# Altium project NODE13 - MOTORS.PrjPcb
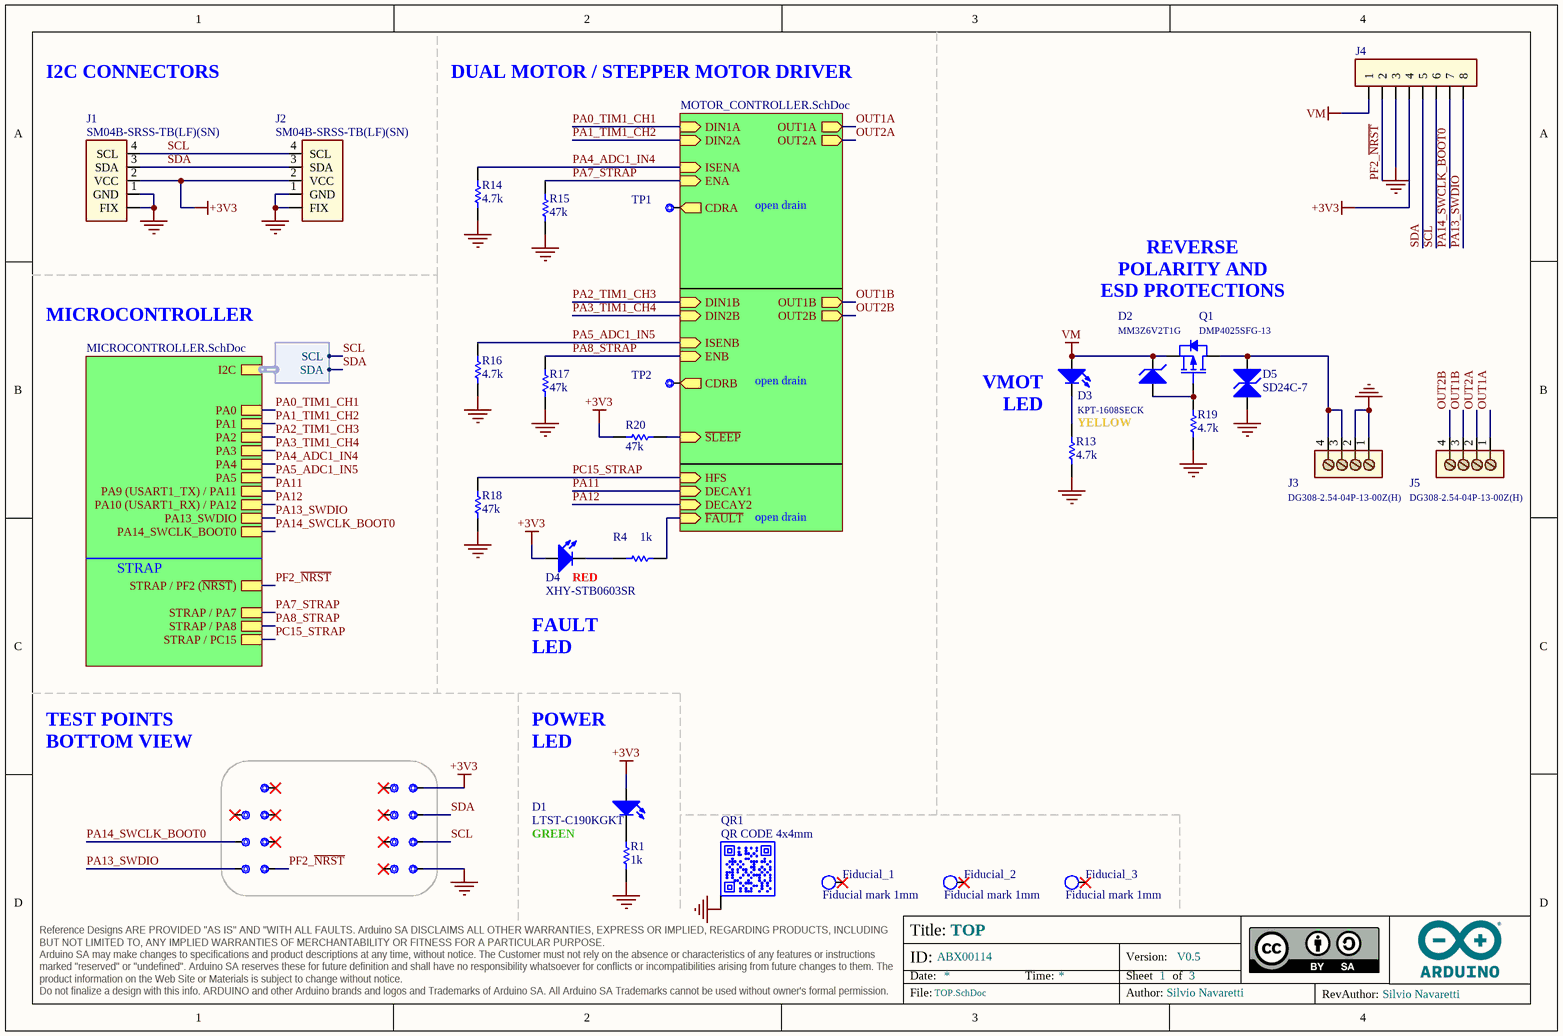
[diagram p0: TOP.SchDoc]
ASSEMBLY_BGA: _; ASSEMBLY_PRESSFIT: _; ASSEMBLY_SMD: X; ASSEMBLY_THT: X; BOARD_CODENAME: NODE 13 MOTOR; BOARD_INFO_AUTHOR: Silvio Navaretti; BOARD_INFO_AUTHOR_REV: Silvio Navaretti; BOARD_INFO_Er: _; BOARD_INFO_FLEX: _; BOARD_INFO_FR4: X; BOARD_INFO_FR4_HTG: _; BOARD_INFO_IPC1: _; BOARD_INFO_IPC2: X; BOARD_INFO_IPC3: _; BOARD_INFO_IPC_NA: _; BOARD_INFO_NUMBER_OF_LAYERS: 2; BOARD_INFO_PCB_SIZE: 41.00x25.36mm; BOARD_INFO_POLYMIDE: _; BOARD_INFO_RIGID: X; BOARD_INFO_RIGID/FLEX: _; BOARD_INFO_TBD: _; BOARD_INFO_THICKNESS: 1.6mm; DRILLS_BLIND: _; DRILLS_BURIED: _; DRILLS_COPPER_FILLING: _; DRILLS_FULL: X; DRILLS_LASER: _; DRILLS_PRESSFIT: _; DRILLS_RESIN_FILLING: _; DRILLS_SLOT: _; DRILLS_SOLDER_FILLING: X; FINISH_ADJUSTMENTS: _; FINISH_EDGE_PLATING: _; FINISH_ENIG: _; FINISH_HAL: _; FINISH_HAL_LF: X; FINISH_NI/AU: _; FINISH_SILK_BOTTOM: X; FINISH_SILK_COLOR: WHITE; FINISH_SILK_TOP: X; FINISH_SN/PB: _; FINISH_SOLDERMASK_BOTTOM: X; FINISH_SOLDERMASK_COLOR: BLUE; FINISH_SOLDERMASK_PEELABLE_BOTTOM: _; FINISH_SOLDERMASK_PEELABLE_COLOR: _; FINISH_SOLDERMASK_PEELABLE_TOP: _; FINISH_SOLDERMASK_TOP: X; FINISH_TABS: _; FINISH_TBD: _; INSULATION_MIN_INNER: 0.15mm; INSULATION_MIN_OUTER: 0.15mm; PANEL_MILLING: X; PANEL_NOT_REQUESTED: _; PANEL_NUMBER_OF_FIGURES: 30; PANEL_PROVIDED: X; PANEL_REQUESTED: _; PANEL_SCORING: X; PANEL_SIZE: 262.00x221.00mm; PANEL_TABS: _; SKU: ABX00114; TRACK_MIN_WIDTH_INNER: 0.15mm; TRACK_MIN_WIDTH_OUTER: 0.15mm; Version: V0.5; VIA_1: _; VIA_1_HOLE_MM: _; VIA_1_PAD_MM: _; VIA_2: _; VIA_2_HOLE_MM: _; VIA_2_PAD_MM: _; VIA_3: _; VIA_3_HOLE_MM: _; VIA_3_PAD_MM: _; VIA_4: _; VIA_4_HOLE_MM: _; VIA_4_PAD_MM: _; VIA_5: _; VIA_5_HOLE_MM: _; VIA_5_PAD_MM: _; VIA_THROUGH: X; VIA_THROUGH_HOLE_MM: 0.3; VIA_THROUGH_PAD_MM: 0.6
3 sheets, 64 parts. Net scope: hierarchical (ports join the sheet entries above them; power ports are global).
Board files: PCB.PcbDoc, PANEL.PcbDoc
Sheets:
  TOP.SchDoc
    U_MOTOR_CONTROLLER = MOTOR_CONTROLLER.SchDoc
    U_MICROCONTROLLER = MICROCONTROLLER.SchDoc

## Sheet TOP.SchDoc: TOP
size A4; Revision: V0.5; SheetNumber: 1; SheetTotal: 3

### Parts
3V3  Test point 1.00mm  [TP-1.00MM]  (value not drawn)  (no BOM)
D1  LTST-C190KGKT  [LEDC1608X80N-AK]
D2  MM3Z6V2T1G  [SOD323]
D3  KPT-1608SECK  [LEDC1608X80N-AK]
D4  XHY-STB0603SR  [LEDC1608X80N-AK]
D5  SD24C-7  [SOD323]
Fiducial_1  Fiducial mark 1mm  [Fiducial mark 1mm-Footprint-1]  (no BOM)
Fiducial_2  Fiducial mark 1mm  [Fiducial mark 1mm-Footprint-1]  (no BOM)
Fiducial_3  Fiducial mark 1mm  [Fiducial mark 1mm-Footprint-1]  (no BOM)
GND  Test point 1.00mm  [TP-1.00MM]  (value not drawn)  (no BOM)
J1  SM04B-SRSS-TB(LF)(SN)  [SM04B-SRSS-TB(LF)(SN)-Footprint-1]
J2  SM04B-SRSS-TB(LF)(SN)  [SM04B-SRSS-TB(LF)(SN)-Footprint-1]
J3  DG308-2.54-04P-13-00Z(H)  [DG308-2.54-04P]
J4  HEADER TH 2.54mm VERT. 1x008POS  [PIN HEADER 2.54mm VERT. 1x8POS]  (value not drawn)  (no BOM)
J5  DG308-2.54-04P-13-00Z(H)  [DG308-2.54-04P]
NRST  Test point 1.00mm  [TP-1.00MM]  (value not drawn)  (no BOM)
PA6  Test point 1.00mm  [TP-1.00MM]  (value not drawn)  (no BOM)
PA7  Test point 1.00mm  [TP-1.00MM]  (value not drawn)  (no BOM)
PC14  Test point 1.00mm  [TP-1.00MM]  (value not drawn)  (no BOM)
PC15  Test point 1.00mm  [TP-1.00MM]  (value not drawn)  (no BOM)
Q1  DMP4025SFG-13  [DMP4025SFG-13]
QR1  QR CODE 4x4mm  [QR CODE 4x4mm]  (no BOM)
R1  value 1k  [RES-0402]  (hidden comment: CRCW04021K00FKEDC)
R4  value 1k  [RES-0402]  (hidden comment: CRCW04021K00FKEDC)
R13  value 4.7k  [RES-0402]  (hidden comment: RC0402FR-074K7L)
R14  value 4.7k  [RES-0402]  (hidden comment: RC0402FR-074K7L)
R15  value 47k  [RES-0402]  (hidden comment: CRCW040247K0FKED)
R16  value 4.7k  [RES-0402]  (hidden comment: RC0402FR-074K7L)
R17  value 47k  [RES-0402]  (hidden comment: CRCW040247K0FKED)
R18  value 47k  [RES-0402]  (hidden comment: CRCW040247K0FKED)
R19  value 4.7k  [RES-0402]  (hidden comment: RC0402FR-074K7L)
R20  value 47k  [RES-0402]  (hidden comment: CRCW040247K0FKED)
SCL  Test point 1.00mm  [TP-1.00MM]  (value not drawn)  (no BOM)
SDA  Test point 1.00mm  [TP-1.00MM]  (value not drawn)  (no BOM)
SWCLK  Test point 1.00mm  [TP-1.00MM]  (value not drawn)  (no BOM)
SWDIO  Test point 1.00mm  [TP-1.00MM]  (value not drawn)  (no BOM)
TP1  Test point 1.00mm  [TP-1.00MM]  (value not drawn)  (no BOM)
TP2  Test point 1.00mm  [TP-1.00MM]  (value not drawn)  (no BOM)
TP9  Test point 1.00mm  [TP-1.00MM]  (value not drawn)  (no BOM)
TP10  Test point 1.00mm  [TP-1.00MM]  (value not drawn)  (no BOM)
TP11  Test point 1.00mm  [TP-1.00MM]  (value not drawn)  (no BOM)
TP12  Test point 1.00mm  [TP-1.00MM]  (value not drawn)  (no BOM)

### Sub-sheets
U_MICROCONTROLLER = MICROCONTROLLER.SchDoc: I2C (harness I2C), PA0, PA1, PA2, PA3, PA4, PA5, PA13_SWDIO, PA14_SWCLK_BOOT0, PA9 (USART1_TX) / PA11, PA10 (USART1_RX) / PA12, STRAP / PF2 (~{NRST}), STRAP / PA8, STRAP / PA7, STRAP / PC15
U_MOTOR_CONTROLLER = MOTOR_CONTROLLER.SchDoc: DIN1A (in), DIN2A (in), DIN1B (in), DIN2B (in), ENA (in), ENB (in), CDRA (out), CDRB (out), OUT1A (out), OUT1B (out), OUT2A (out), OUT2B (out), ISENA (in), ISENB (in), ~{FAULT} (in), DECAY1 (in), DECAY2 (in), HFS (in), ~{SLEEP} (in)

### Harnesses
I2C: SDA, SCL

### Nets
+3V3: 3V3.X D1.A D4.A J1.2(VCC) J2.2(VCC) J4.4 R20.2
GND: D5.1(A1) GND.X J1.1(GND) J1.FIX J2.1(GND) J2.FIX J3.1 J3.2 J4.3 QR1.PAD R1.1 R13.1 R14.1 R15.1 R16.1 R17.1 R18.1 R19.1
VM: D2.C D3.A J4.1 Q1.S
OUT1A: J5.1 ; sheet U_MOTOR_CONTROLLER/OUT1A
OUT1B: J5.3 ; sheet U_MOTOR_CONTROLLER/OUT1B
OUT2A: J5.2 ; sheet U_MOTOR_CONTROLLER/OUT2A
OUT2B: J5.4 ; sheet U_MOTOR_CONTROLLER/OUT2B
PA0_TIM1_CH1: sheet U_MOTOR_CONTROLLER/DIN1A, sheet U_MICROCONTROLLER/PA0
PA1_TIM1_CH2: sheet U_MOTOR_CONTROLLER/DIN2A, sheet U_MICROCONTROLLER/PA1
PA2_TIM1_CH3: sheet U_MOTOR_CONTROLLER/DIN1B, sheet U_MICROCONTROLLER/PA2
PA3_TIM1_CH4: sheet U_MOTOR_CONTROLLER/DIN2B, sheet U_MICROCONTROLLER/PA3
PA4_ADC1_IN4: R14.2 ; sheet U_MOTOR_CONTROLLER/ISENA, sheet U_MICROCONTROLLER/PA4
PA5_ADC1_IN5: R16.2 ; sheet U_MOTOR_CONTROLLER/ISENB, sheet U_MICROCONTROLLER/PA5
PA7_STRAP: R15.2 ; sheet U_MOTOR_CONTROLLER/ENA, sheet U_MICROCONTROLLER/STRAP / PA7  [project net PA7]
PA8_STRAP: R17.2 ; sheet U_MOTOR_CONTROLLER/ENB, sheet U_MICROCONTROLLER/STRAP / PA8  [project net PA8]
PA11: sheet U_MOTOR_CONTROLLER/DECAY1, sheet U_MICROCONTROLLER/PA9 (USART1_TX) / PA11
PA12: sheet U_MOTOR_CONTROLLER/DECAY2, sheet U_MICROCONTROLLER/PA10 (USART1_RX) / PA12
PA13_SWDIO: J4.8 SWCLK.X ; sheet U_MICROCONTROLLER/PA13_SWDIO
PA14_SWCLK_BOOT0: J4.7 SWDIO.X ; sheet U_MICROCONTROLLER/PA14_SWCLK_BOOT0
PC15_STRAP: R18.2 ; sheet U_MOTOR_CONTROLLER/HFS, sheet U_MICROCONTROLLER/STRAP / PC15  [project net PC15]
PF2_~{NRST}: J4.2 NRST.X ; sheet U_MICROCONTROLLER/STRAP / PF2 (~{NRST})
SCL: J1.4(SCL) J2.4(SCL) J4.6 SCL.X ; sheet U_MICROCONTROLLER/I2C.SCL
SDA: J1.3(SDA) J2.3(SDA) J4.5 SDA.X ; sheet U_MICROCONTROLLER/I2C.SDA
NetD1_C: D1.C R1.2
NetD2_A: D2.A Q1.G R19.2
NetD3_C: D3.C R13.2
NetD4_C: D4.C R4.2
NetD5_2: D5.2(A2) J3.3 J3.4 Q1.D
NetR4_1: R4.1 ; sheet U_MOTOR_CONTROLLER/~{FAULT}
NetR20_1: R20.1 ; sheet U_MOTOR_CONTROLLER/~{SLEEP}
NetTP1_X: TP1.X ; sheet U_MOTOR_CONTROLLER/CDRA
NetTP2_X: TP2.X ; sheet U_MOTOR_CONTROLLER/CDRB

Not connected (* = marked no-connect by the designer): Fiducial_1 1*; Fiducial_2 1*; Fiducial_3 1*; PA6 X*; PA7 X*; PC14 X*; PC15 X*; TP9 X*; TP10 X*; TP11 X*; TP12 X*

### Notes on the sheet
- I2C CONNECTORS
- DUAL MOTOR / STEPPER MOTOR DRIVER
- open drain
- REVERSE POLARITY AND ESD PROTECTIONS
- MICROCONTROLLER
- VMOT
  LED
- (near R13) YELLOW
- STRAP
- (near D4) RED
- FAULT LED
- TEST POINTS BOTTOM VIEW
- (near D1) POWER LED
- GREEN

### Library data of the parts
3V3 GND NRST PA6 PA7 PC14 PC15 SCL SDA SWCLK SWDIO TP1 TP2 TP9-TP12 = UT0013-A.6: Manufacturer: This is not a component
D1 = L0009-A.6: LED SMD 0603 GREEN/568 15mcd 120^; Manufacturer: Liteon; Code Arduino: 2204
D2 = D0086-3: DIODE ZENER SMD 6V2 0.2W SOD323; Manufacturer: OnSemi; Vzener typ: 6.2V; Vzener max: 6.6V; Code Arduino: D0086; Vzener min: 5.8V; Power max: 200mW; Ireverse max: 3µA; Vforward max: 900mV
D3 = L0006-A.5: LED SMD 0603 ORANGE601 250mcd 120^; Manufacturer: Kingbright; Code Arduino: 2207
D4 = L0024-A.4: LED SMD 0603 RED 625nm, water clear, 42 to 88 mcd, 120 degrees, 1.6x0.8x0.6mm; Manufacturer: Shenzen Corehy Technology; Code Arduino: L0024
D5 = D0085-A.1: DIODE TVS BIDIRECTIONAL 24V 70V SOD323; Manufacturer: Diodes Incorporated; Code Arduino: D0085
Fiducial_1-Fiducial_3 = UT0023-A.7: Fiducial mark 1mm clearance 2mm
J1 J2 = J0005-A.3: CONN JST SH 1mm 4POS HORIZONTAL TIN QWIIC; Code Arduino: J0005
J3 J5 = J0438-A.5: CONN SCREW TERMINAL 4 POS pitch 2.54mm height 8.6mm BLACK; Manufacturer: Degson; Code Arduino: J0438
J4 = J0171-A.4: Code Arduino: J0171
Q1 = T0059-A.2: MOSFET P-CH Vds -40V, Vgs +-20V, RdsON 45mR at Vgs -4.5V, 3.3x3.3x0.8mm DFN; Manufacturer: Diodes Incorporated; Code Arduino: T0059; Drain to Source Voltage (Vdss): 40V; Gate to Source Voltage (Vgs): 10V
QR1 = QR-0001-A.5: QR CODE 4x4mm on layer 34 (This is not a component); Code Arduino: QRCODE_4x4mm
R1 R4 = R0007-A.24: RES CHIP 0402 1k 1% 1/16W; Manufacturer: Vishay; Code Arduino: 0140; Power: 62.5mW; Temperature coefficient: 100ppm
R13 R14 R16 R19 = R0013-A.24: RES CHIP 0402 4k7 1% 1/16W; Manufacturer: YAGEO; Code Arduino: 2196; Power: 62.5mW; Temperature coefficient: 200ppm
R15 R17 R18 R20 = R0051-A.24: RES CHIP 0402 47k 1% 1/16W; Manufacturer: Vishay; Code Arduino: A5339; Power: 62.5mW; Temperature coefficient: 200ppm

## Sheet MOTOR_CONTROLLER.SchDoc: MOTOR CONTROLLER
size A4; SheetNumber: 3; SheetTotal: 3
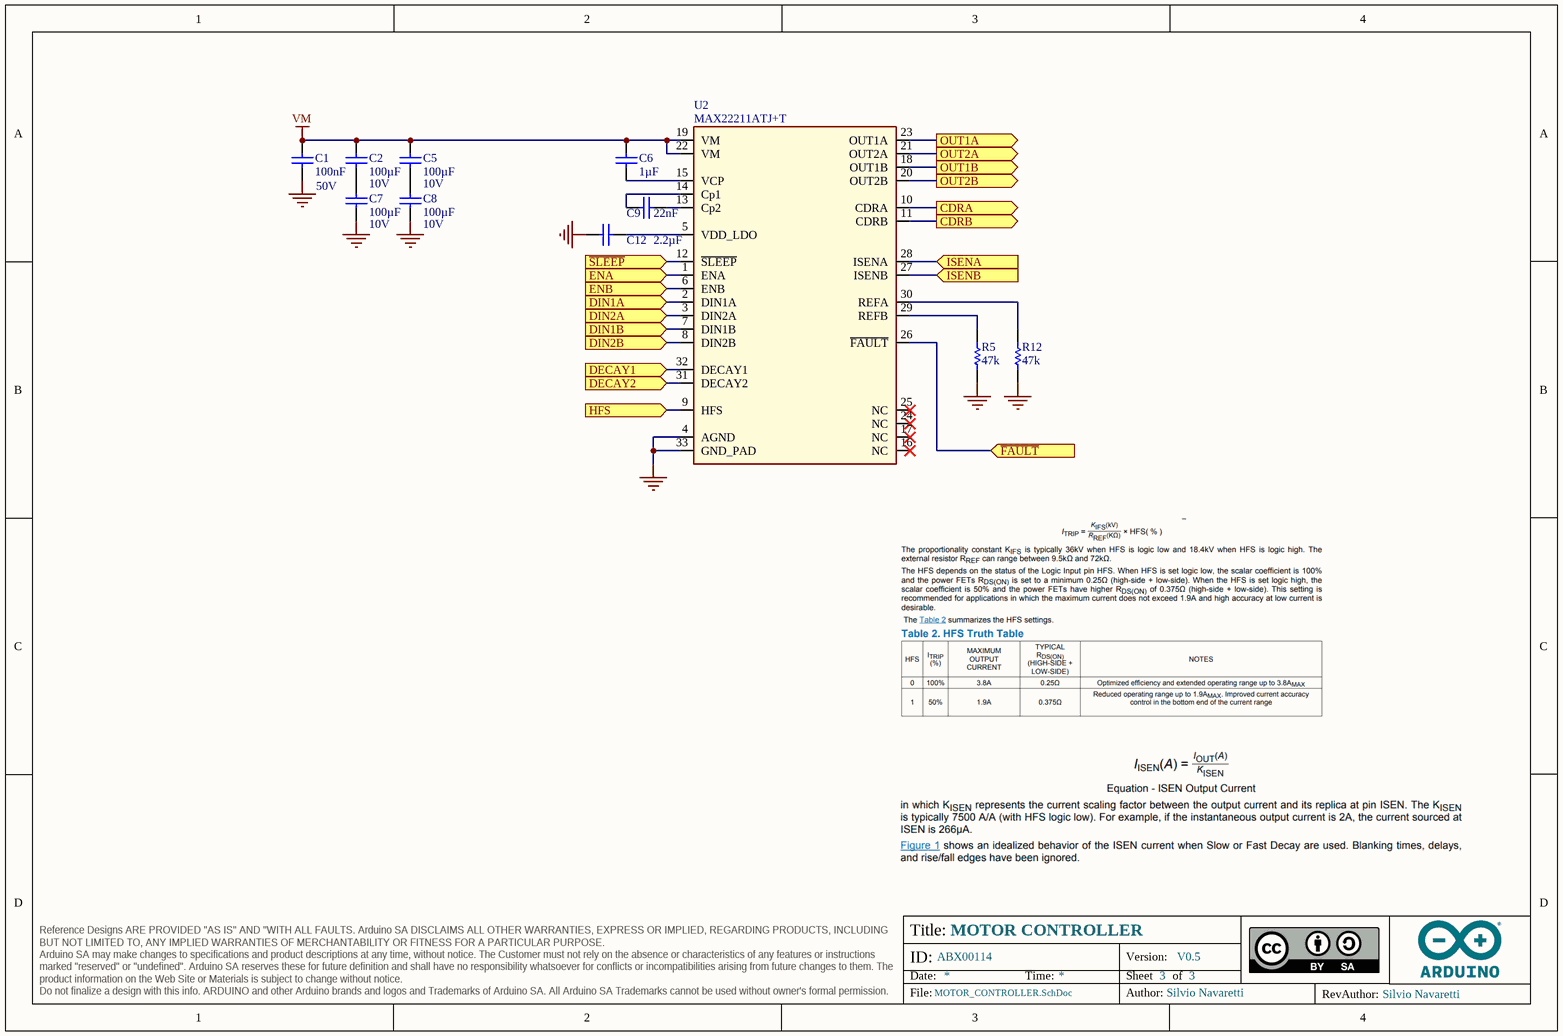
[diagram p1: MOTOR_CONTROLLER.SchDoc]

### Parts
C1  value 100nF  Voltage: 50V  [CAP-0402]  (hidden comment: GRM155R61H104KE19D)
C2  value 100µF  Voltage: 10V  [CAP-1206]  (hidden comment: GRM31CR61A107MEA8L)
C5  value 100µF  Voltage: 10V  [CAP-1206]  (hidden comment: GRM31CR61A107MEA8L)
C6  value 1µF  [CAP-0603]  (hidden comment: GRM188R61E105KA12J)
C7  value 100µF  Voltage: 10V  [CAP-1206]  (hidden comment: GRM31CR61A107MEA8L)
C8  value 100µF  Voltage: 10V  [CAP-1206]  (hidden comment: GRM31CR61A107MEA8L)
C9  value 22nF  [CAP-0402]  (hidden comment: CL05B223KB5VPNC)
C12  value 2.2µF  [CAP-0402]  (hidden comment: CC0402MRX5R5BB225)
R5  value 47k  [RES-0402]  (hidden comment: CRCW040247K0FKED)
R12  value 47k  [RES-0402]  (hidden comment: CRCW040247K0FKED)
U2  MAX22211ATJ+T  [QFN127P600-8N]

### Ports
CDRA (out), CDRB (out), DECAY1 (in), DECAY2 (in), DIN1A (in), DIN1B (in), DIN2A (in), DIN2B (in), ENA (in), ENB (in), HFS (in), ISENA (in), ISENB (in), OUT1A (out), OUT1B (out), OUT2A (out), OUT2B (out), ~{FAULT} (in), ~{SLEEP} (in)

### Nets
GND: C1.1 C7.2 C8.2 C12.1 R5.1 R12.1 U2.4(AGND) U2.33(GND_PAD)
VM: C1.2 C2.1 C5.1 C6.1 U2.19(VM) U2.22(VM)
OUT1A: U2.23(OUT1A) ; port OUT1A
OUT1B: U2.18(OUT1B) ; port OUT1B
OUT2A: U2.21(OUT2A) ; port OUT2A
OUT2B: U2.20(OUT2B) ; port OUT2B
PA0_TIM1_CH1: U2.2(DIN1A) ; port DIN1A
PA1_TIM1_CH2: U2.3(DIN2A) ; port DIN2A
PA2_TIM1_CH3: U2.7(DIN1B) ; port DIN1B
PA3_TIM1_CH4: U2.8(DIN2B) ; port DIN2B
PA4_ADC1_IN4: U2.28(ISENA) ; port ISENA
PA5_ADC1_IN5: U2.27(ISENB) ; port ISENB
PA7: U2.1(ENA) ; port ENA
PA8: U2.6(ENB) ; port ENB
PA11: U2.32(DECAY1) ; port DECAY1
PA12: U2.31(DECAY2) ; port DECAY2
PC15: U2.9(HFS) ; port HFS
NetC2_2: C2.2 C7.1
NetC5_2: C5.2 C8.1
NetC6_2: C6.2 U2.15(VCP)
NetC9_1: C9.1 U2.13(Cp2)
NetC9_2: C9.2 U2.14(Cp1)
NetC12_2: C12.2 U2.5(VDD_LDO)
NetR4_1: U2.26(~{FAULT}) ; port ~{FAULT}
NetR5_2: R5.2 U2.29(REFB)
NetR12_2: R12.2 U2.30(REFA)
NetR20_1: U2.12(~{SLEEP}) ; port ~{SLEEP}
NetTP1_X: U2.10(CDRA) ; port CDRA
NetTP2_X: U2.11(CDRB) ; port CDRB

Not connected (* = marked no-connect by the designer): U2 16(NC)* 17(NC)* 24(NC)* 25(NC)*

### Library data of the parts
C1 = C0015-A.14: CAP CHIP 0402 100nF 10% 50V X5R; Manufacturer: Murata; Code Arduino: A5141
C2 C5 C7 C8 = C0166-A.1: CAP CHIP 1206 100uF 20% 10V X5R; Manufacturer: Murata; Code Arduino: C0166
C6 = C0044-A.14: CAP CHIP 0603 1uF 10% 25V X5R; Manufacturer: Murata; Code Arduino: 0006
C9 = C0119-A.8: CAP CHIP 0402 22nF 10% 50V X7R; Manufacturer: Samsung Electro-Mechanics; Code Arduino: C0119
C12 = C0076-A.13: CAP CHIP 0402 2.2uF 20% 6.3V; Manufacturer: Yageo; Code Arduino: A5334; Dielectric: X5R
R5 R12 = R0051-A.24: as R15 on sheet TOP
U2 = U0300-A.2: 36V, 3.8A Two H-Bridge for Dual Brushed or Single Stepper Motor Drive; Manufacturer: Analoge Device; Code Arduino: U0300

## Sheet MICROCONTROLLER.SchDoc: MICROCONTROLLER
size A4; SheetNumber: 2; SheetTotal: 3
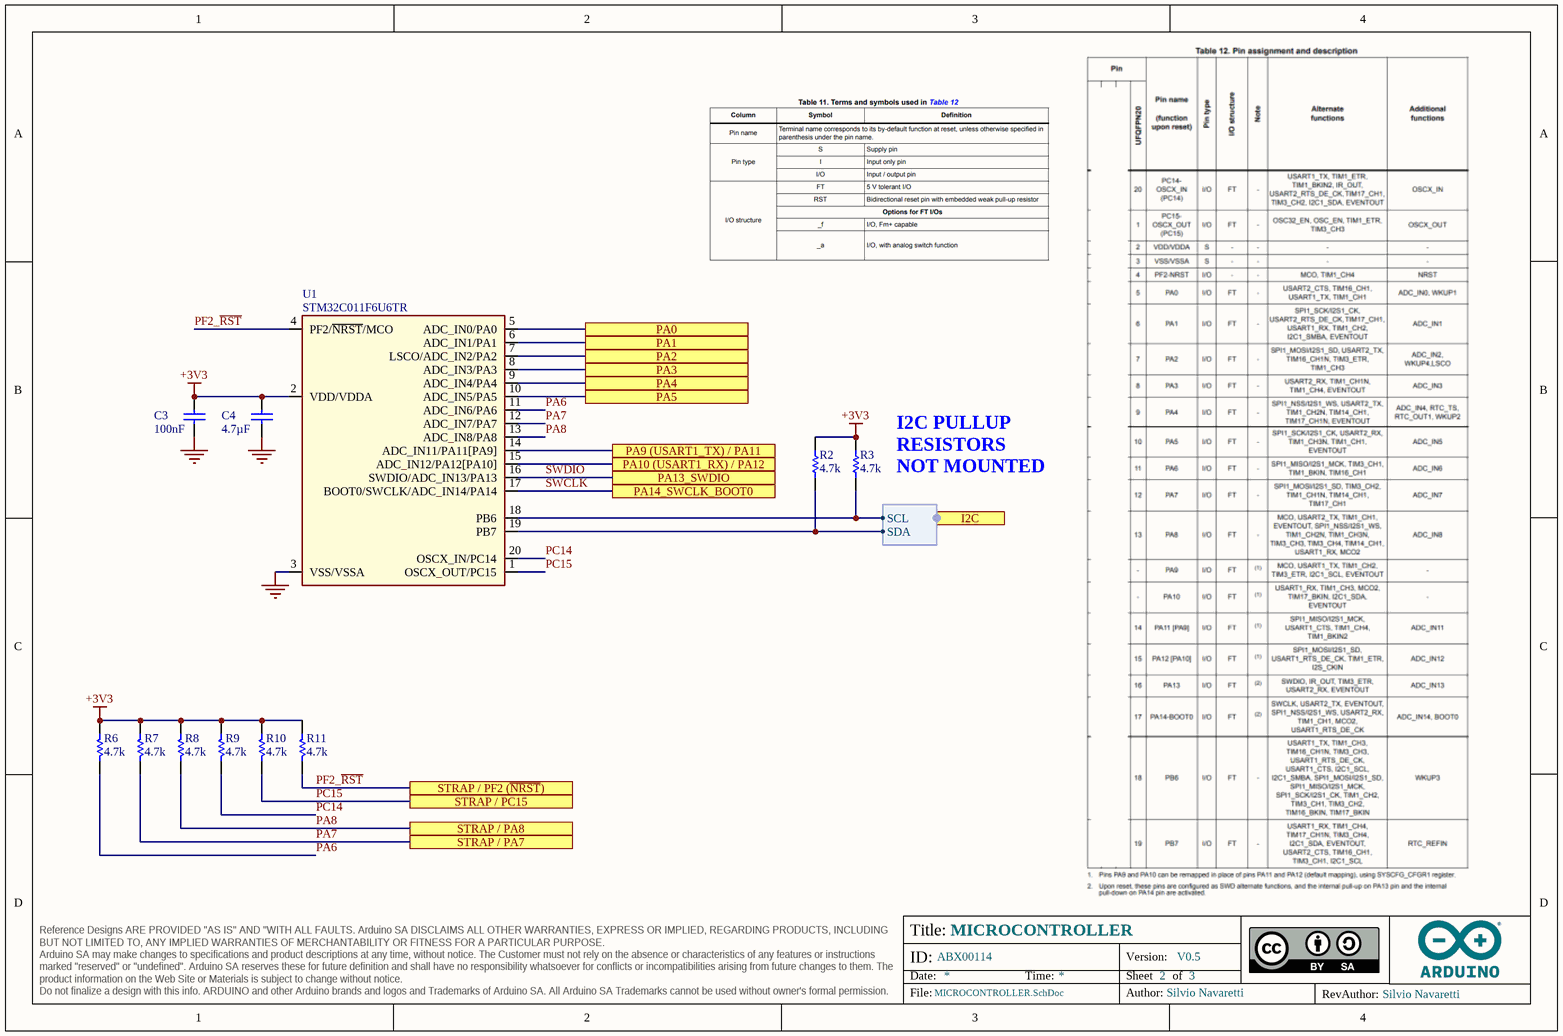
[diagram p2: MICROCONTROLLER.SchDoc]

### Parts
C3  value 100nF  [CAP-0402]  (hidden comment: 0402B104K160CT)
C4  value 4.7µF  [CAP-0603]  (hidden comment: GRM188R61C475KAAJD)
R2  value 4.7k  [RES-0402]  (hidden comment: RC0402FR-074K7L)
R3  value 4.7k  [RES-0402]  (hidden comment: RC0402FR-074K7L)
R6  value 4.7k  [RES-0402]  (hidden comment: RC0402FR-074K7L)
R7  value 4.7k  [RES-0402]  (hidden comment: RC0402FR-074K7L)
R8  value 4.7k  [RES-0402]  (hidden comment: RC0402FR-074K7L)
R9  value 4.7k  [RES-0402]  (hidden comment: RC0402FR-074K7L)
R10  value 4.7k  [RES-0402]  (hidden comment: RC0402FR-074K7L)
R11  value 4.7k  [RES-0402]  (hidden comment: RC0402FR-074K7L)
U1  STM32C011F6U6TR  [UFQFPN20]

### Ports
I2C (harness I2C), PA0, PA1, PA2, PA3, PA4, PA5, PA9 (USART1_TX) / PA11, PA10 (USART1_RX) / PA12, PA13_SWDIO, PA14_SWCLK_BOOT0, STRAP / PA7, STRAP / PA8, STRAP / PC15, STRAP / PF2 (~{NRST})

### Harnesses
I2C: SDA, SCL

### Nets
+3V3: C3.1 C4.2 R2.2 R3.2 R6.1 R7.1 R8.1 R9.1 R10.1 R11.1 U1.2(VDD/VDDA)
GND: C3.2 C4.1 U1.3(VSS/VSSA)
PA0_TIM1_CH1: U1.5(ADC_IN0/PA0) ; port PA0
PA1_TIM1_CH2: U1.6(ADC_IN1/PA1) ; port PA1
PA2_TIM1_CH3: U1.7(LSCO/ADC_IN2/PA2) ; port PA2
PA3_TIM1_CH4: U1.8(ADC_IN3/PA3) ; port PA3
PA4_ADC1_IN4: U1.9(ADC_IN4/PA4) ; port PA4
PA5_ADC1_IN5: U1.10(ADC_IN5/PA5) ; port PA5
PA6: R6.2 U1.11(ADC_IN6/PA6)  [project net PA6_2]
PA7: R7.2 U1.12(ADC_IN7/PA7) ; port STRAP / PA7
PA8: R8.2 U1.13(ADC_IN8/PA8) ; port STRAP / PA8
PA11: U1.14(ADC_IN11/PA11[PA9]) ; port PA9 (USART1_TX) / PA11
PA12: U1.15(ADC_IN12/PA12[PA10]) ; port PA10 (USART1_RX) / PA12
PC14: R9.2 U1.20(OSCX_IN/PC14)  [project net PC14_2]
PC15: R10.2 U1.1(OSCX_OUT/PC15) ; port STRAP / PC15
PF2_~{RST}: R11.2 U1.4(PF2/~{NRST}/MCO) ; port STRAP / PF2 (~{NRST})  [project net PF2_~{NRST}]
SCL: R3.1 U1.18(PB6) ; port I2C.SCL
SDA: R2.1 U1.19(PB7) ; port I2C.SDA
SWCLK: U1.17(BOOT0/SWCLK/ADC_IN14/PA14) ; port PA14_SWCLK_BOOT0  [project net PA14_SWCLK_BOOT0]
SWDIO: U1.16(SWDIO/ADC_IN13/PA13) ; port PA13_SWDIO  [project net PA13_SWDIO]

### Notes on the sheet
- (near R3) I2C PULLUP RESISTORS NOT MOUNTED

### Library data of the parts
C3 = C0012-A.15: CAP CHIP 0402 100nF 10% 16V X7R; Manufacturer: Walsin; Code Arduino: 0132
C4 = C0054-A.16: CAP CHIP 0603 4.7uF 10% 16V X5R; Manufacturer: Murata; Code Arduino: A5072
R2 R3 = R0013-A.24: as R13 on sheet TOP
R6-R11 = R0013-A.24: RES CHIP 0402 4k7 1% 1/16W; Manufacturer: YAGEO; Power: 62.5mW; Code Arduino: 2196; Temperature coefficient: 200ppm
U1 = U0390-A.1: IC Cortex M0, 32b MCU, 32KB Flash, 6KB RAM, VDD 2-3.6V, -40°C to 85°C, QFN20 3x3mm; Manufacturer: ST Microelectronics; Code Arduino: U0390

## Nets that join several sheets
+3V3: TOP (7 pins), MICROCONTROLLER (11 pins)
GND: TOP (18 pins), MOTOR_CONTROLLER (8 pins), MICROCONTROLLER (C3.2 C4.1 U1.3)
VM: TOP (D2.C D3.A J4.1 Q1.S), MOTOR_CONTROLLER (6 pins)
NetR4_1: TOP (R4.1), MOTOR_CONTROLLER (U2.26)
NetR20_1: TOP (R20.1), MOTOR_CONTROLLER (U2.12)
NetTP1_X: TOP (TP1.X), MOTOR_CONTROLLER (U2.10)
NetTP2_X: TOP (TP2.X), MOTOR_CONTROLLER (U2.11)
OUT1A: TOP (J5.1), MOTOR_CONTROLLER (U2.23)
OUT1B: TOP (J5.3), MOTOR_CONTROLLER (U2.18)
OUT2A: TOP (J5.2), MOTOR_CONTROLLER (U2.21)
OUT2B: TOP (J5.4), MOTOR_CONTROLLER (U2.20)
PA0_TIM1_CH1: MOTOR_CONTROLLER (U2.2), MICROCONTROLLER (U1.5)
PA1_TIM1_CH2: MOTOR_CONTROLLER (U2.3), MICROCONTROLLER (U1.6)
PA2_TIM1_CH3: MOTOR_CONTROLLER (U2.7), MICROCONTROLLER (U1.7)
PA3_TIM1_CH4: MOTOR_CONTROLLER (U2.8), MICROCONTROLLER (U1.8)
PA4_ADC1_IN4: TOP (R14.2), MOTOR_CONTROLLER (U2.28), MICROCONTROLLER (U1.9)
PA5_ADC1_IN5: TOP (R16.2), MOTOR_CONTROLLER (U2.27), MICROCONTROLLER (U1.10)
PA7: TOP (R15.2), MOTOR_CONTROLLER (U2.1), MICROCONTROLLER (R7.2 U1.12)
PA8: TOP (R17.2), MOTOR_CONTROLLER (U2.6), MICROCONTROLLER (R8.2 U1.13)
PA11: MOTOR_CONTROLLER (U2.32), MICROCONTROLLER (U1.14)
PA12: MOTOR_CONTROLLER (U2.31), MICROCONTROLLER (U1.15)
PA13_SWDIO: TOP (J4.8 SWCLK.X), MICROCONTROLLER (U1.16)
PA14_SWCLK_BOOT0: TOP (J4.7 SWDIO.X), MICROCONTROLLER (U1.17)
PC15: TOP (R18.2), MOTOR_CONTROLLER (U2.9), MICROCONTROLLER (R10.2 U1.1)
PF2_~{NRST}: TOP (J4.2 NRST.X), MICROCONTROLLER (R11.2 U1.4)
SCL: TOP (J1.4 J2.4 J4.6 SCL.X), MICROCONTROLLER (R3.1 U1.18)
SDA: TOP (J1.3 J2.3 J4.5 SDA.X), MICROCONTROLLER (R2.1 U1.19)

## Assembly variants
ABX00114: not fitted R2 R3 R7 R8 R10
